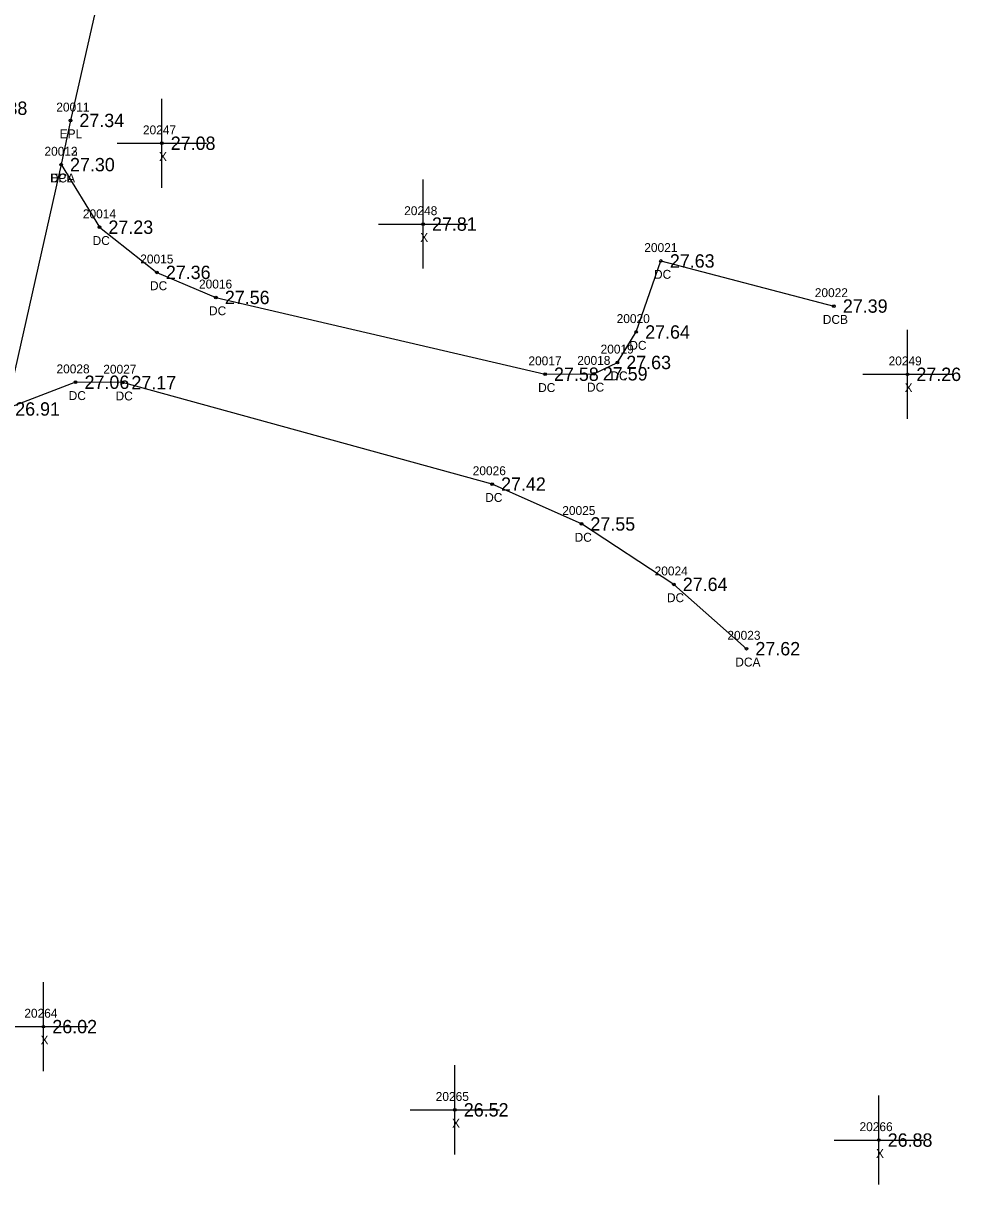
# Model space of a CAD drawing. Extents: x 2655177 to 2656219, y 761780 to 764748.
# Drawn here: x 2656013 to 2656118.1, y 764400.6 to 764533.5 of the extents above; entities that cross this region are included whole.
import ezdxf

# ---------------------------------------------------------------- set-up
doc = ezdxf.new("R2010")
doc.units = 0
for name, color, linetype in [('RD_EX_Conc', 7, 'Continuous'), ('RD_EX_Conc_txCode', 7, 'Continuous'), ('RD_EX_Misc', 7, 'Continuous'), ('RD_EX_Misc_txCode', 7, 'Continuous'), ('RD_EX_Road', 7, 'Continuous'), ('RD_EX_Road_txCode', 7, 'Continuous'), ('RD_EX_TX_Conc_ELEV', 7, 'Continuous'), ('RD_EX_TX_Misc_ELEV', 7, 'Continuous'), ('RD_EX_TX_Road_ELEV', 7, 'Continuous'), ('RD_HC_Survey_ELEV', 7, 'Continuous'), ('RD_SMD_Locator', 7, 'Continuous')]:
    doc.layers.add(name, color=color, linetype=linetype)

msp = doc.modelspace()

# ---------------------------------------------------------------- linework, layer by layer
at = {"layer": 'RD_EX_Conc'}
for points in [[(2656017.22, 764517.64), (2656021.53, 764510.62), (2656027.97, 764505.55), (2656034.59, 764502.74), (2656071.52, 764494.12), (2656077, 764494.17), (2656079.63, 764495.44), (2656081.75, 764498.86), (2656084.52, 764506.83), (2656103.93, 764501.77)], [(2656094.12, 764463.32), (2656085.97, 764470.54), (2656075.61, 764477.32), (2656065.58, 764481.79), (2656024.11, 764493.18), (2656018.85, 764493.22), (2656011.07, 764490.22)]]:
    msp.add_lwpolyline(points, dxfattribs=at)
at = {"layer": 'RD_EX_Misc'}
for p, q in [((2656028.52, 764515.04), (2656028.52, 764525.04)), ((2656023.52, 764520.04), (2656033.52, 764520.04)), ((2656057.83, 764505.97), (2656057.83, 764515.97)), ((2656052.83, 764510.97), (2656062.83, 764510.97)), ((2656112.18, 764489.11), (2656112.18, 764499.11)), ((2656107.18, 764494.11), (2656117.18, 764494.11)), ((2656015.23, 764415.91), (2656015.23, 764425.91)), ((2656010.23, 764420.91), (2656020.23, 764420.91)), ((2656061.4, 764406.57), (2656061.4, 764416.57)), ((2656108.96, 764403.18), (2656108.96, 764413.18)), ((2656056.4, 764411.57), (2656066.4, 764411.57)), ((2656103.96, 764408.18), (2656113.96, 764408.18))]:
    msp.add_line(p, q, dxfattribs=at)
at = {"layer": 'RD_EX_Road'}
msp.add_lwpolyline([(2656062.87, 764717.57), (2656039.84, 764617.04), (2656035.41, 764597.94), (2656033.38, 764589.18), (2656018.27, 764522.6), (2656017.22, 764517.64), (2656011.07, 764490.22), (2655996.52, 764425.63), (2655974.03, 764327.02), (2655960.71, 764269.34), (2655951.96, 764231.59), (2655930.84, 764138.62), (2655926.81, 764121.01)], dxfattribs=at)
at = {"layer": 'RD_SMD_Locator'}
for centre in [(2656018.27, 764522.6), (2656028.52, 764520.04), (2656017.22, 764517.64), (2656017.22, 764517.64), (2656057.83, 764510.97), (2656021.53, 764510.62), (2656084.52, 764506.83), (2656027.97, 764505.55), (2656034.59, 764502.74), (2656103.93, 764501.77), (2656081.75, 764498.86), (2656079.63, 764495.44), (2656071.52, 764494.12), (2656077, 764494.17), (2656112.18, 764494.11), (2656018.85, 764493.22), (2656024.11, 764493.18), (2656065.58, 764481.79), (2656075.61, 764477.32), (2656085.97, 764470.54), (2656094.12, 764463.32), (2656015.23, 764420.91), (2656061.4, 764411.57), (2656108.96, 764408.18)]:
    msp.add_circle(centre, 0.15, dxfattribs=at)

# ---------------------------------------------------------------- texts
at = {"layer": 'RD_EX_Conc_txCode'}
for s, p in [('20013', (2656015.35, 764518.64)), ('DCA', (2656015.96, 764515.64)), ('20014', (2656019.66, 764511.62)), ('DC', (2656020.75, 764508.62)), ('20021', (2656082.65, 764507.83)), ('20015', (2656026.1, 764506.55)), ('DC', (2656083.74, 764504.83)), ('DC', (2656027.19, 764503.55)), ('20016', (2656032.69, 764503.74)), ('20022', (2656101.78, 764502.77)), ('DC', (2656033.81, 764500.74)), ('20020', (2656079.55, 764499.86)), ('DCB', (2656102.68, 764499.77)), ('DC', (2656080.97, 764496.86)), ('20019', (2656077.75, 764496.44)), ('20028', (2656016.7, 764494.22)), ('20027', (2656021.95, 764494.18)), ('20017', (2656069.65, 764495.12)), ('20018', (2656075.13, 764495.17)), ('DC', (2656078.85, 764493.44)), ('DC', (2656070.74, 764492.12)), ('DC', (2656076.22, 764492.17)), ('DC', (2656018.07, 764491.22)), ('DC', (2656023.33, 764491.18)), ('20026', (2656063.4, 764482.79)), ('DC', (2656064.8, 764479.79)), ('20025', (2656073.45, 764478.32)), ('DC', (2656074.83, 764475.32)), ('20024', (2656083.81, 764471.54)), ('DC', (2656085.19, 764468.54)), ('20023', (2656091.97, 764464.32)), ('DCA', (2656092.86, 764461.32))]:
    msp.add_text(s, height=1, dxfattribs=at).set_placement(p)
at = {"layer": 'RD_EX_Misc_txCode'}
for s, p in [('20247', (2656026.4, 764521.04)), ('X', (2656028.2, 764518.04)), ('20248', (2656055.71, 764511.97)), ('X', (2656057.51, 764508.97)), ('20249', (2656110.06, 764495.11)), ('X', (2656111.86, 764492.11)), ('20264', (2656013.09, 764421.91)), ('X', (2656014.91, 764418.91)), ('20265', (2656059.25, 764412.57)), ('X', (2656061.08, 764409.57)), ('20266', (2656106.8, 764409.18)), ('X', (2656108.65, 764406.18))]:
    msp.add_text(s, height=1, dxfattribs=at).set_placement(p)
at = {"layer": 'RD_EX_Road_txCode'}
for s, p in [('20011', (2656016.68, 764523.6)), ('EPL', (2656017.06, 764520.6)), ('20012', (2656015.35, 764518.64)), ('EPL', (2656016.02, 764515.64))]:
    msp.add_text(s, height=1, dxfattribs=at).set_placement(p)
at = {"layer": 'RD_EX_TX_Conc_ELEV'}
for s, p in [('27.30', (2656018.22, 764516.89)), ('27.23', (2656022.53, 764509.87)), ('27.63', (2656085.52, 764506.08)), ('27.36', (2656028.97, 764504.8)), ('27.56', (2656035.59, 764501.99)), ('27.39', (2656104.93, 764501.02)), ('27.64', (2656082.75, 764498.11)), ('27.63', (2656080.63, 764494.69)), ('27.06', (2656019.85, 764492.47)), ('27.17', (2656025.11, 764492.43)), ('27.58', (2656072.52, 764493.37)), ('27.59', (2656078, 764493.42)), ('26.91', (2656012.07, 764489.47)), ('27.42', (2656066.58, 764481.04)), ('27.55', (2656076.61, 764476.57)), ('27.64', (2656086.97, 764469.79)), ('27.62', (2656095.12, 764462.57))]:
    msp.add_text(s, height=1.5, dxfattribs=at).set_placement(p)
at = {"layer": 'RD_EX_TX_Misc_ELEV'}
for s, p in [('27.08', (2656029.52, 764519.29)), ('27.81', (2656058.83, 764510.22)), ('27.26', (2656113.18, 764493.36)), ('26.02', (2656016.23, 764420.16)), ('26.52', (2656062.4, 764410.82)), ('26.88', (2656109.96, 764407.43))]:
    msp.add_text(s, height=1.5, dxfattribs=at).set_placement(p)
at = {"layer": 'RD_EX_TX_Road_ELEV'}
for s, p in [('27.34', (2656019.27, 764521.85)), ('27.30', (2656018.22, 764516.89)), ('26.91', (2656012.07, 764489.47))]:
    msp.add_text(s, height=1.5, dxfattribs=at).set_placement(p)
at = {"layer": 'RD_HC_Survey_ELEV'}
msp.add_text('27.38', height=1.5, dxfattribs=at).set_placement((2656008.41, 764523.22))

doc.saveas('drawing.dxf')
